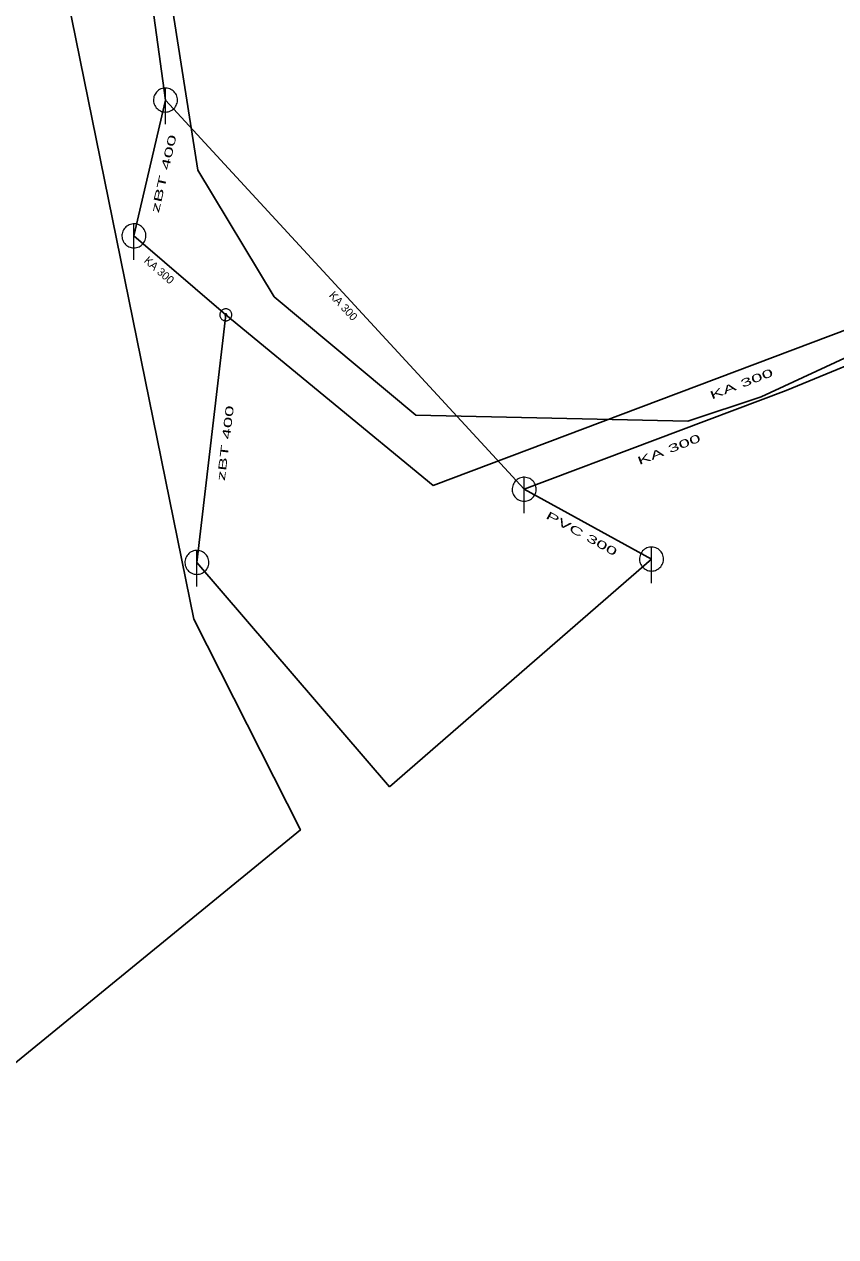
# Model space of a CAD drawing. Extents: x -688432 to -687974, y -973332 to -972704.
# Drawn here: x -688148.9 to -688081.3, y -973102.6 to -973001.6 of the extents above; entities that cross this region are included whole.
import ezdxf
from ezdxf.enums import TextEntityAlignment as Align

# ---------------------------------------------------------------- set-up
doc = ezdxf.new("R2010")
doc.units = 0
doc.header["$LTSCALE"] = 0.27
for name, color, linetype, lineweight in [('1', 7, 'Continuous', 25), ('14', 7, 'Continuous', 25), ('17', 7, 'Continuous', 25), ('22', 7, 'Continuous', 13), ('31', 7, 'Continuous', 13)]:
    doc.layers.add(name, color=color, linetype=linetype, lineweight=lineweight)

msp = doc.modelspace()

# ---------------------------------------------------------------- linework, layer by layer
at = {"layer": '14'}
for p, q in [((-688134.528, -973046.412), (-688132.125, -973025.78)), ((-688096.66, -973046.13), (-688107.27, -973040.32)), ((-688118.48, -973065.11), (-688134.529, -973046.413)), ((-688118.48, -973065.11), (-688096.66, -973046.13))]:
    msp.add_line(p, q, dxfattribs=at)
for points in [[(-688132.125, -973025.78), (-688139.776, -973019.199), (-688137.15, -973007.88), (-688140.466, -972983.669)], [(-688066.854, -973024.418), (-688085.44, -973032.099), (-688107.27, -973040.32), (-688137.15, -973007.88)], [(-688064.425, -973020.969), (-688114.84, -973040.004), (-688132.125, -973025.78)]]:
    msp.add_lwpolyline(points, dxfattribs=at)
at = {"layer": '17'}
for points in [[(-688123.609, -972815.609), (-688135.91, -972839.761), (-688146.524, -972867.704), (-688149.164, -972878.87), (-688150.368, -972974.473), (-688134.778, -973051.136), (-688125.903, -973068.701), (-688203.651, -973132.27), (-688148.612, -973199.748), (-688078.631, -973291.807), (-688049.631, -973331.642)], [(-688050.85, -973016.992), (-688055.169, -973017.307), (-688064.057, -973021.728), (-688087.539, -973032.609), (-688093.627, -973034.653), (-688116.302, -973034.144), (-688128.092, -973024.28), (-688134.442, -973013.736), (-688141.05, -972971.647), (-688145.326, -972926.979)]]:
    msp.add_lwpolyline(points, dxfattribs=at)
at = {"layer": '22'}
for p, q in [((-688137.15, -973009.88), (-688137.149, -973006.88)), ((-688139.776, -973021.2), (-688139.775, -973018.2)), ((-688107.27, -973042.32), (-688107.269, -973039.32)), ((-688134.529, -973048.413), (-688134.528, -973045.413)), ((-688096.66, -973048.13), (-688096.659, -973045.13))]:
    msp.add_line(p, q, dxfattribs=at)
for points in [[(-688136.15, -973007.88), (-688136.155, -973007.771), (-688136.173, -973007.663), (-688136.203, -973007.557), (-688136.243, -973007.456), (-688136.295, -973007.359), (-688136.357, -973007.269), (-688136.429, -973007.186), (-688136.509, -973007.112), (-688136.597, -973007.046), (-688136.691, -973006.991), (-688136.791, -973006.946), (-688136.896, -973006.913), (-688137.003, -973006.891), (-688137.112, -973006.881), (-688137.222, -973006.883), (-688137.33, -973006.897), (-688137.437, -973006.922), (-688137.54, -973006.959), (-688137.638, -973007.008), (-688137.73, -973007.066), (-688137.816, -973007.135), (-688137.893, -973007.212), (-688137.962, -973007.298), (-688138.021, -973007.39), (-688138.069, -973007.488), (-688138.106, -973007.591), (-688138.132, -973007.698), (-688138.146, -973007.806), (-688138.149, -973007.916), (-688138.139, -973008.025), (-688138.118, -973008.132), (-688138.084, -973008.236), (-688138.04, -973008.336), (-688137.985, -973008.431), (-688137.919, -973008.519), (-688137.845, -973008.599), (-688137.762, -973008.671), (-688137.672, -973008.733), (-688137.576, -973008.785), (-688137.474, -973008.826), (-688137.369, -973008.856), (-688137.261, -973008.874), (-688137.151, -973008.88), (-688137.042, -973008.874), (-688136.934, -973008.856), (-688136.829, -973008.827), (-688136.727, -973008.786), (-688136.63, -973008.734), (-688136.54, -973008.672), (-688136.457, -973008.601), (-688136.382, -973008.521), (-688136.317, -973008.433), (-688136.261, -973008.339), (-688136.217, -973008.239), (-688136.183, -973008.135), (-688136.161, -973008.027), (-688136.151, -973007.918)], [(-688138.776, -973019.2), (-688138.781, -973019.091), (-688138.799, -973018.983), (-688138.829, -973018.877), (-688138.869, -973018.776), (-688138.921, -973018.679), (-688138.983, -973018.589), (-688139.055, -973018.506), (-688139.135, -973018.432), (-688139.223, -973018.366), (-688139.317, -973018.311), (-688139.417, -973018.266), (-688139.522, -973018.233), (-688139.629, -973018.211), (-688139.738, -973018.201), (-688139.848, -973018.203), (-688139.956, -973018.217), (-688140.063, -973018.242), (-688140.166, -973018.279), (-688140.264, -973018.328), (-688140.356, -973018.386), (-688140.442, -973018.455), (-688140.519, -973018.532), (-688140.588, -973018.618), (-688140.647, -973018.71), (-688140.695, -973018.808), (-688140.732, -973018.911), (-688140.758, -973019.018), (-688140.772, -973019.126), (-688140.775, -973019.236), (-688140.765, -973019.345), (-688140.744, -973019.452), (-688140.71, -973019.556), (-688140.666, -973019.656), (-688140.611, -973019.751), (-688140.545, -973019.839), (-688140.471, -973019.919), (-688140.388, -973019.991), (-688140.298, -973020.053), (-688140.202, -973020.105), (-688140.1, -973020.146), (-688139.995, -973020.176), (-688139.887, -973020.194), (-688139.777, -973020.2), (-688139.668, -973020.194), (-688139.56, -973020.176), (-688139.455, -973020.147), (-688139.353, -973020.106), (-688139.256, -973020.054), (-688139.166, -973019.992), (-688139.083, -973019.921), (-688139.008, -973019.841), (-688138.943, -973019.753), (-688138.887, -973019.659), (-688138.843, -973019.559), (-688138.809, -973019.455), (-688138.787, -973019.347), (-688138.777, -973019.238)], [(-688106.27, -973040.32), (-688106.275, -973040.211), (-688106.293, -973040.103), (-688106.323, -973039.997), (-688106.363, -973039.896), (-688106.415, -973039.799), (-688106.477, -973039.709), (-688106.549, -973039.626), (-688106.629, -973039.552), (-688106.717, -973039.486), (-688106.811, -973039.431), (-688106.911, -973039.386), (-688107.016, -973039.353), (-688107.123, -973039.331), (-688107.232, -973039.321), (-688107.342, -973039.323), (-688107.45, -973039.337), (-688107.557, -973039.362), (-688107.66, -973039.399), (-688107.758, -973039.448), (-688107.85, -973039.506), (-688107.936, -973039.575), (-688108.013, -973039.652), (-688108.082, -973039.738), (-688108.141, -973039.83), (-688108.189, -973039.928), (-688108.226, -973040.031), (-688108.252, -973040.138), (-688108.266, -973040.246), (-688108.269, -973040.356), (-688108.259, -973040.465), (-688108.238, -973040.572), (-688108.204, -973040.676), (-688108.16, -973040.776), (-688108.105, -973040.871), (-688108.039, -973040.959), (-688107.965, -973041.039), (-688107.882, -973041.111), (-688107.792, -973041.173), (-688107.696, -973041.225), (-688107.594, -973041.266), (-688107.489, -973041.296), (-688107.381, -973041.314), (-688107.271, -973041.32), (-688107.162, -973041.314), (-688107.054, -973041.296), (-688106.949, -973041.267), (-688106.847, -973041.226), (-688106.75, -973041.174), (-688106.66, -973041.112), (-688106.577, -973041.041), (-688106.502, -973040.961), (-688106.437, -973040.873), (-688106.381, -973040.779), (-688106.337, -973040.679), (-688106.303, -973040.575), (-688106.281, -973040.467), (-688106.271, -973040.358)], [(-688133.529, -973046.413), (-688133.534, -973046.304), (-688133.552, -973046.196), (-688133.582, -973046.09), (-688133.622, -973045.989), (-688133.674, -973045.892), (-688133.736, -973045.802), (-688133.808, -973045.719), (-688133.888, -973045.645), (-688133.976, -973045.579), (-688134.07, -973045.524), (-688134.17, -973045.479), (-688134.275, -973045.446), (-688134.382, -973045.424), (-688134.491, -973045.414), (-688134.601, -973045.416), (-688134.709, -973045.43), (-688134.816, -973045.455), (-688134.919, -973045.492), (-688135.017, -973045.541), (-688135.109, -973045.599), (-688135.195, -973045.668), (-688135.272, -973045.745), (-688135.341, -973045.831), (-688135.4, -973045.923), (-688135.448, -973046.021), (-688135.485, -973046.124), (-688135.511, -973046.231), (-688135.525, -973046.339), (-688135.528, -973046.449), (-688135.518, -973046.558), (-688135.497, -973046.665), (-688135.463, -973046.769), (-688135.419, -973046.869), (-688135.364, -973046.964), (-688135.298, -973047.052), (-688135.224, -973047.132), (-688135.141, -973047.204), (-688135.051, -973047.266), (-688134.955, -973047.318), (-688134.853, -973047.359), (-688134.748, -973047.389), (-688134.64, -973047.407), (-688134.53, -973047.413), (-688134.421, -973047.407), (-688134.313, -973047.389), (-688134.208, -973047.36), (-688134.106, -973047.319), (-688134.009, -973047.267), (-688133.919, -973047.205), (-688133.836, -973047.134), (-688133.761, -973047.054), (-688133.696, -973046.966), (-688133.64, -973046.872), (-688133.596, -973046.772), (-688133.562, -973046.668), (-688133.54, -973046.56), (-688133.53, -973046.451)], [(-688095.66, -973046.13), (-688095.665, -973046.021), (-688095.683, -973045.913), (-688095.713, -973045.807), (-688095.753, -973045.706), (-688095.805, -973045.609), (-688095.867, -973045.519), (-688095.939, -973045.436), (-688096.019, -973045.362), (-688096.107, -973045.296), (-688096.201, -973045.241), (-688096.301, -973045.196), (-688096.406, -973045.163), (-688096.513, -973045.141), (-688096.622, -973045.131), (-688096.732, -973045.133), (-688096.84, -973045.147), (-688096.947, -973045.172), (-688097.05, -973045.209), (-688097.148, -973045.258), (-688097.24, -973045.316), (-688097.326, -973045.385), (-688097.403, -973045.462), (-688097.472, -973045.548), (-688097.531, -973045.64), (-688097.579, -973045.738), (-688097.616, -973045.841), (-688097.642, -973045.948), (-688097.656, -973046.056), (-688097.659, -973046.166), (-688097.649, -973046.275), (-688097.628, -973046.382), (-688097.594, -973046.486), (-688097.55, -973046.586), (-688097.495, -973046.681), (-688097.429, -973046.769), (-688097.355, -973046.849), (-688097.272, -973046.921), (-688097.182, -973046.983), (-688097.086, -973047.035), (-688096.984, -973047.076), (-688096.879, -973047.106), (-688096.771, -973047.124), (-688096.661, -973047.13), (-688096.552, -973047.124), (-688096.444, -973047.106), (-688096.339, -973047.077), (-688096.237, -973047.036), (-688096.14, -973046.984), (-688096.05, -973046.922), (-688095.967, -973046.851), (-688095.892, -973046.771), (-688095.827, -973046.683), (-688095.771, -973046.589), (-688095.727, -973046.489), (-688095.693, -973046.385), (-688095.671, -973046.277), (-688095.661, -973046.168)]]:
    msp.add_lwpolyline(points, close=True, dxfattribs=at)
at = {"layer": '31'}
for points in [[(-688132.511, -973025.462), (-688132.541, -973025.504), (-688132.568, -973025.549), (-688132.589, -973025.597), (-688132.606, -973025.646), (-688132.618, -973025.697), (-688132.623, -973025.75), (-688132.623, -973025.802), (-688132.618, -973025.854), (-688132.608, -973025.905), (-688132.593, -973025.955), (-688132.572, -973026.003), (-688132.545, -973026.048), (-688132.516, -973026.091), (-688132.48, -973026.13), (-688132.442, -973026.166), (-688132.4, -973026.196), (-688132.355, -973026.223), (-688132.307, -973026.245), (-688132.258, -973026.261), (-688132.207, -973026.273), (-688132.154, -973026.278), (-688132.102, -973026.279), (-688132.049, -973026.274), (-688131.999, -973026.264), (-688131.949, -973026.248), (-688131.901, -973026.227), (-688131.855, -973026.201), (-688131.813, -973026.171), (-688131.774, -973026.135), (-688131.738, -973026.097), (-688131.708, -973026.055), (-688131.681, -973026.01), (-688131.658, -973025.962), (-688131.643, -973025.913), (-688131.631, -973025.862), (-688131.625, -973025.81), (-688131.624, -973025.757), (-688131.629, -973025.705), (-688131.64, -973025.654), (-688131.656, -973025.604), (-688131.677, -973025.556), (-688131.702, -973025.51), (-688131.733, -973025.468), (-688131.769, -973025.429), (-688131.807, -973025.393), (-688131.849, -973025.363), (-688131.894, -973025.336), (-688131.941, -973025.314), (-688131.991, -973025.298), (-688132.042, -973025.286), (-688132.094, -973025.28), (-688132.146, -973025.28), (-688132.198, -973025.285), (-688132.25, -973025.296), (-688132.3, -973025.311), (-688132.348, -973025.332), (-688132.393, -973025.358), (-688132.436, -973025.388), (-688132.475, -973025.424)], [(-688132.188, -973025.727), (-688132.194, -973025.734), (-688132.197, -973025.742), (-688132.201, -973025.749), (-688132.203, -973025.757), (-688132.205, -973025.766), (-688132.206, -973025.775), (-688132.207, -973025.783), (-688132.206, -973025.792), (-688132.204, -973025.8), (-688132.201, -973025.808), (-688132.198, -973025.816), (-688132.193, -973025.824), (-688132.188, -973025.83), (-688132.184, -973025.837), (-688132.177, -973025.843), (-688132.17, -973025.849), (-688132.162, -973025.852), (-688132.155, -973025.856), (-688132.147, -973025.858), (-688132.138, -973025.86), (-688132.129, -973025.861), (-688132.121, -973025.862), (-688132.112, -973025.861), (-688132.103, -973025.859), (-688132.096, -973025.856), (-688132.088, -973025.853), (-688132.08, -973025.848), (-688132.074, -973025.843), (-688132.067, -973025.839), (-688132.061, -973025.832), (-688132.055, -973025.825), (-688132.052, -973025.817), (-688132.048, -973025.81), (-688132.046, -973025.802), (-688132.044, -973025.793), (-688132.042, -973025.785), (-688132.042, -973025.776), (-688132.043, -973025.767), (-688132.045, -973025.758), (-688132.048, -973025.751), (-688132.051, -973025.743), (-688132.056, -973025.735), (-688132.061, -973025.729), (-688132.065, -973025.722), (-688132.072, -973025.716), (-688132.079, -973025.71), (-688132.087, -973025.707), (-688132.094, -973025.703), (-688132.102, -973025.701), (-688132.111, -973025.699), (-688132.119, -973025.697), (-688132.128, -973025.697), (-688132.137, -973025.698), (-688132.145, -973025.7), (-688132.153, -973025.703), (-688132.161, -973025.706), (-688132.169, -973025.711), (-688132.175, -973025.716), (-688132.182, -973025.72)]]:
    msp.add_lwpolyline(points, close=True, dxfattribs=at)

# ---------------------------------------------------------------- texts
at = {"layer": '1'}
for s, rotation, width, p in [('zBT 400 ', 77, 2, (-688136.9113, -973013.855)), ('zBT 400 ', 77, 2, (-688136.9113, -973013.855)), ('zBT 400 ', 77, 2, (-688136.9113, -973013.855)), ('zBT 400 ', 77, 2, (-688136.9113, -973013.855)), ('zBT 400 ', 77, 2, (-688136.9113, -973013.855)), ('KA 300', 21, 1.9, (-688089.0505, -973031.8433)), ('KA 300', 21, 1.9, (-688089.0505, -973031.8433)), ('KA 300', 21, 1.9, (-688089.0505, -973031.8433)), ('KA 300', 21, 1.9, (-688089.0505, -973031.8433)), ('KA 300', 21, 1.9, (-688089.0505, -973031.8433)), ('zBT 400 ', 83, 1.9, (-688131.8006, -973036.2846)), ('zBT 400 ', 83, 1.9, (-688131.8006, -973036.2846)), ('zBT 400 ', 83, 1.9, (-688131.8006, -973036.2846)), ('zBT 400 ', 83, 1.9, (-688131.8006, -973036.2846)), ('zBT 400 ', 83, 1.9, (-688131.8006, -973036.2846)), ('KA 300', 21, 1.9, (-688095.0905, -973037.3043)), ('KA 300', 21, 1.9, (-688095.0905, -973037.3043)), ('KA 300', 21, 1.9, (-688095.0905, -973037.3043)), ('KA 300', 21, 1.9, (-688095.0905, -973037.3043)), ('KA 300', 21, 1.9, (-688095.0905, -973037.3043)), ('PVC 300 ', 331, 1.85, (-688102.4406, -973044.4174)), ('PVC 300 ', 331, 1.85, (-688102.4406, -973044.4174)), ('PVC 300 ', 331, 1.85, (-688102.4406, -973044.4174)), ('PVC 300 ', 331, 1.85, (-688102.4406, -973044.4174)), ('PVC 300 ', 331, 1.85, (-688102.4406, -973044.4174))]:
    msp.add_text(s, height=0.6667, rotation=rotation, dxfattribs=dict(at, width=width)).set_placement(p, align=Align.CENTER)
for rotation, p in [(319, (-688137.8921, -973022.3145)), (319, (-688137.8921, -973022.3145)), (319, (-688137.8921, -973022.3145)), (319, (-688137.8921, -973022.3145)), (319, (-688137.8921, -973022.3145)), (313, (-688122.5765, -973025.2717)), (313, (-688122.5765, -973025.2717)), (313, (-688122.5765, -973025.2717)), (313, (-688122.5765, -973025.2717)), (313, (-688122.5765, -973025.2717))]:
    msp.add_text('KA 300', height=0.6667, rotation=rotation, dxfattribs=at).set_placement(p, align=Align.CENTER)

doc.saveas('drawing.dxf')
